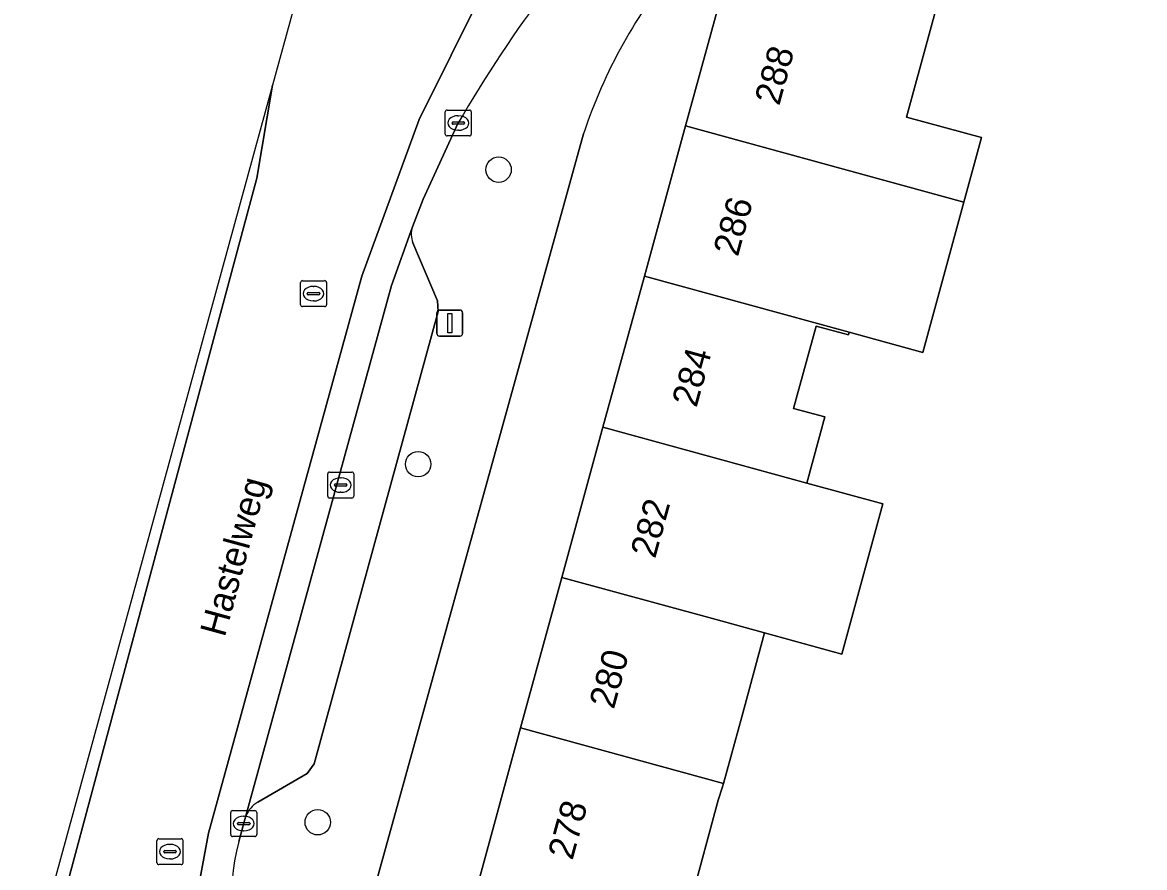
# Model space of a CAD drawing. Extents: x 158086 to 159499, y 382904 to 383981.
# Drawn here: x 158109.87 to 158153.07, y 383168.66 to 383201.21 of the extents above; entities that cross this region are included whole.
import ezdxf

# ---------------------------------------------------------------- set-up
doc = ezdxf.new("R2010")
doc.units = 0
for name, color, linetype in [('IMGEO_Boom', 7, 'Continuous'), ('IMGEO_Erf', 7, 'Continuous'), ('IMGEO_Kolk', 7, 'Continuous'), ('IMGEO_Lichtmast', 7, 'Continuous'), ('IMGEO_Openbare_ruimte_label', 7, 'Continuous'), ('IMGEO_Pand', 7, 'Continuous'), ('IMGEO_Pand_nummerreeks', 7, 'Continuous'), ('IMGEO_Parkeervlak_open', 7, 'Continuous'), ('IMGEO_Rijbaan_lokaal_gesloten', 7, 'Continuous'), ('IMGEO_Rioolput', 7, 'Continuous'), ('IMGEO_Voetpad_open', 7, 'Continuous')]:
    doc.layers.add(name, color=color, linetype=linetype)

msp = doc.modelspace()

# ---------------------------------------------------------------- linework, layer by layer
at = {"layer": 'IMGEO_Boom'}
for centre in [(158128.198, 383195.54), (158125.102, 383184.199), (158121.236, 383170.41)]:
    msp.add_circle(centre, 0.489, dxfattribs=at)
at = {"layer": 'IMGEO_Erf'}
for points in [[(158145.614, 383203.826), (158143.901, 383197.567), (158146.795, 383196.776), (158146.115, 383194.289), (158144.532, 383188.501), (158141.69, 383189.278), (158141.663, 383189.18), (158140.426, 383189.519), (158139.557, 383186.348), (158140.763, 383186.017), (158140.066, 383183.473), (158142.994, 383182.671), (158141.406, 383176.886), (158138.441, 383177.7), (158137.559, 383174.463), (158136.856, 383171.899), (158136.823, 383171.777), (158136.657, 383171.255), (158135.955, 383168.694), (158135.236, 383166.071), (158133.867, 383161.076), (158144.952, 383157.529), (158146.228, 383161.583), (158153.322, 383159.318)], [(158124.547, 383163.99), (158125.14, 383163.802), (158130.42, 383162.036), (158131.785, 383167.017), (158127.445, 383168.206), (158129.043, 383174.04), (158130.633, 383179.84), (158132.217, 383185.624), (158133.81, 383191.437), (158135.396, 383197.227), (158136.998, 383203.073)], [(158131.469, 383196.918), (158123.046, 383166.519)]]:
    msp.add_lwpolyline(points, dxfattribs=at)
msp.add_arc((158150.374, 383190.692), 19.904, 139.9318, 161.7716, dxfattribs=at)
at = {"layer": 'IMGEO_Kolk'}
for p, q in [((158126.147, 383196.912), (158126.147, 383197.764)), ((158126.222, 383197.838), (158127.074, 383197.838)), ((158126.635, 383197.618), (158126.66, 383197.618)), ((158127.148, 383197.764), (158127.148, 383196.912)), ((158126.406, 383197.332), (158126.406, 383197.344)), ((158126.844, 383197.295), (158126.446, 383197.295)), ((158126.449, 383197.381), (158126.847, 383197.381)), ((158126.89, 383197.344), (158126.89, 383197.332)), ((158127.074, 383196.838), (158126.222, 383196.838)), ((158126.658, 383197.058), (158126.633, 383197.058)), ((158121.62, 383182.97), (158121.62, 383183.822)), ((158121.695, 383183.896), (158122.547, 383183.896)), ((158122.621, 383183.822), (158122.621, 383182.97)), ((158121.879, 383183.39), (158121.879, 383183.402)), ((158122.317, 383183.353), (158121.919, 383183.353)), ((158121.922, 383183.439), (158122.32, 383183.439)), ((158122.108, 383183.676), (158122.133, 383183.676)), ((158122.363, 383183.402), (158122.363, 383183.39)), ((158122.547, 383182.896), (158121.695, 383182.896)), ((158122.131, 383183.116), (158122.106, 383183.116)), ((158117.887, 383169.932), (158117.887, 383170.784)), ((158117.962, 383170.858), (158118.814, 383170.858)), ((158118.888, 383170.784), (158118.888, 383169.932)), ((158118.146, 383170.352), (158118.146, 383170.364)), ((158118.189, 383170.401), (158118.587, 383170.401)), ((158118.375, 383170.638), (158118.4, 383170.638)), ((158118.63, 383170.364), (158118.63, 383170.352)), ((158118.584, 383170.315), (158118.186, 383170.315)), ((158118.398, 383170.078), (158118.373, 383170.078)), ((158118.814, 383169.858), (158117.962, 383169.858))]:
    msp.add_line(p, q, dxfattribs=at)
for points in [[(158126.147, 383196.912), (158126.147, 383197.764)], [(158126.222, 383197.838), (158127.074, 383197.838)], [(158127.148, 383197.764), (158127.148, 383196.912)], [(158127.074, 383196.838), (158126.222, 383196.838)], [(158121.62, 383182.97), (158121.62, 383183.822)], [(158121.695, 383183.896), (158122.547, 383183.896)], [(158122.621, 383183.822), (158122.621, 383182.97)], [(158122.547, 383182.896), (158121.695, 383182.896)], [(158117.887, 383169.932), (158117.887, 383170.784)], [(158117.962, 383170.858), (158118.814, 383170.858)], [(158118.888, 383170.784), (158118.888, 383169.932)], [(158118.814, 383169.858), (158117.962, 383169.858)]]:
    msp.add_lwpolyline(points, dxfattribs=at)
for centre, radius, start, end in [((158126.224, 383197.762), 0.0765, 91.552, 178.448), ((158126.224, 383197.762), 0.0765, 91.552, 178.448), ((158127.072, 383197.762), 0.0765, 1.552, 88.448), ((158127.072, 383197.762), 0.0765, 1.552, 88.448), ((158126.446, 383197.341), 0.0403, 85.8775, 175.7526), ((158126.443, 383197.331), 0.0366, 178.938, 274.7102), ((158126.847, 383197.338), 0.043, 264.8664, 352.4533), ((158126.851, 383197.343), 0.0386, 1.7309, 96.639), ((158126.224, 383196.914), 0.0765, 181.552, 268.448), ((158126.224, 383196.914), 0.0765, 181.552, 268.448), ((158127.072, 383196.914), 0.0765, 271.552, 358.448), ((158127.072, 383196.914), 0.0765, 271.552, 358.448), ((158121.697, 383183.82), 0.0765, 91.552, 178.448), ((158121.697, 383183.82), 0.0765, 91.552, 178.448), ((158122.545, 383183.82), 0.0765, 1.552, 88.448), ((158122.545, 383183.82), 0.0765, 1.552, 88.448), ((158121.919, 383183.399), 0.0403, 85.8775, 175.7526), ((158121.916, 383183.389), 0.0366, 178.938, 274.7102), ((158122.32, 383183.396), 0.043, 264.8664, 352.4533), ((158122.324, 383183.401), 0.0386, 1.7309, 96.639), ((158121.697, 383182.972), 0.0765, 181.552, 268.448), ((158121.697, 383182.972), 0.0765, 181.552, 268.448), ((158122.545, 383182.972), 0.0765, 271.552, 358.448), ((158122.545, 383182.972), 0.0765, 271.552, 358.448), ((158117.964, 383170.782), 0.0765, 91.552, 178.448), ((158117.964, 383170.782), 0.0765, 91.552, 178.448), ((158118.812, 383170.782), 0.0765, 1.552, 88.448), ((158118.812, 383170.782), 0.0765, 1.552, 88.448), ((158118.186, 383170.361), 0.0403, 85.8775, 175.7526), ((158118.183, 383170.351), 0.0366, 178.938, 274.7102), ((158118.587, 383170.358), 0.043, 264.8664, 352.4533), ((158118.591, 383170.363), 0.0386, 1.7309, 96.639), ((158117.964, 383169.934), 0.0765, 181.552, 268.448), ((158117.964, 383169.934), 0.0765, 181.552, 268.448), ((158118.812, 383169.934), 0.0765, 271.552, 358.448), ((158118.812, 383169.934), 0.0765, 271.552, 358.448)]:
    msp.add_arc(centre, radius, start, end, dxfattribs=at)
for centre, major_axis, ratio, start_param, end_param in [((158126.634, 383197.338), (-0.387, 0.002), 0.722429, 4.712389, 7.853982), ((158126.659, 383197.338), (-0.39, 0.002), 0.717154, 1.570796, 4.712389), ((158122.107, 383183.396), (-0.387, 0.002), 0.722429, 4.712389, 7.853982), ((158122.132, 383183.396), (-0.39, 0.002), 0.717154, 1.570796, 4.712389), ((158118.374, 383170.358), (-0.387, 0.002), 0.722429, 4.712389, 7.853982), ((158118.399, 383170.358), (-0.39, 0.002), 0.717154, 1.570796, 4.712389)]:
    msp.add_ellipse(centre, major_axis=major_axis, ratio=ratio, start_param=start_param, end_param=end_param, dxfattribs=at)
at = {"layer": 'IMGEO_Lichtmast'}
for p, q in [((158125.824, 383189.233), (158125.824, 383190.033)), ((158125.824, 383190.033), (158125.824, 383189.233)), ((158125.924, 383190.133), (158126.714, 383190.133)), ((158126.714, 383190.133), (158125.924, 383190.133)), ((158126.814, 383190.033), (158126.814, 383189.233)), ((158126.814, 383189.233), (158126.814, 383190.033)), ((158126.714, 383189.133), (158125.924, 383189.133)), ((158125.924, 383189.133), (158126.714, 383189.133))]:
    msp.add_line(p, q, dxfattribs=at)
msp.add_lwpolyline([(158126.244, 383190.008), (158126.394, 383190.008), (158126.394, 383189.258), (158126.244, 383189.258), (158126.244, 383190.008)], dxfattribs=at)
for centre, start, end in [((158125.924, 383190.033), 90, 180), ((158125.924, 383190.033), 90, 180), ((158126.714, 383190.033), 0, 90), ((158126.714, 383190.033), 360, 90), ((158125.924, 383189.233), 180, 270), ((158125.924, 383189.233), 180, 270), ((158126.714, 383189.233), 270, 0), ((158126.714, 383189.233), 270, 0)]:
    msp.add_arc(centre, 0.1, start, end, dxfattribs=at)
at = {"layer": 'IMGEO_Pand'}
for points in [[(158135.396, 383197.227), (158146.115, 383194.289), (158146.795, 383196.776), (158143.901, 383197.567), (158145.614, 383203.826), (158141.177, 383205.04), (158140.384, 383202.146), (158136.998, 383203.073)], [(158146.115, 383194.289), (158135.396, 383197.227), (158133.81, 383191.437), (158141.69, 383189.278), (158144.532, 383188.501)], [(158140.066, 383183.473), (158140.763, 383186.017), (158139.557, 383186.348), (158140.426, 383189.519), (158141.663, 383189.18), (158141.69, 383189.278), (158133.81, 383191.437), (158132.217, 383185.624)], [(158142.994, 383182.671), (158140.066, 383183.473), (158132.217, 383185.624), (158130.633, 383179.84), (158136.43, 383178.251), (158138.441, 383177.7), (158141.406, 383176.886)], [(158138.441, 383177.7), (158136.43, 383178.251), (158130.633, 383179.84), (158129.043, 383174.04), (158136.856, 383171.899), (158137.559, 383174.463)], [(158136.856, 383171.899), (158129.043, 383174.04), (158127.445, 383168.206), (158131.785, 383167.017), (158130.42, 383162.036), (158133.867, 383161.076), (158135.236, 383166.071), (158135.955, 383168.694), (158136.657, 383171.255), (158136.823, 383171.777)]]:
    msp.add_lwpolyline(points, close=True, dxfattribs=at)
at = {"layer": 'IMGEO_Parkeervlak_open'}
for points in [[(158124.881, 383193.345), (158124.08, 383191.076), (158118.475, 383170.654)], [(158118.926, 383171.179), (158120.832, 383172.293), (158121.096, 383172.659), (158125.876, 383190.077), (158125.846, 383190.485), (158124.904, 383192.718)]]:
    msp.add_lwpolyline(points, dxfattribs=at)
for centre, radius, start, end in [((158125.75, 383193.063), 0.914, 162.0162, 202.1854), ((158119.47, 383170.256), 1.071, 120.4898, 158.1819)]:
    msp.add_arc(centre, radius, start, end, dxfattribs=at)
at = {"layer": 'IMGEO_Rijbaan_lokaal_gesloten'}
for points in [[(158124.452, 383206.638), (158124.819, 383209.324), (158122.442, 383209.544), (158119.498, 383198.799), (158118.896, 383195.213), (158111.593, 383168.013), (158111.383, 383166.817), (158111.299, 383165.033), (158111.404, 383163.963), (158111.855, 383161.854), (158112.421, 383160.267), (158113.174, 383158.889), (158113.975, 383157.813), (158114.447, 383157.32), (158121.663, 383155.026)], [(158121.663, 383155.026), (158123.545, 383158.624), (158121.299, 383159.472), (158120.511, 383159.893), (158119.732, 383160.433), (158118.989, 383161.105), (158118.281, 383161.896), (158117.694, 383162.772), (158117.166, 383163.887), (158116.819, 383164.93), (158116.651, 383166.022), (158116.603, 383167.245), (158116.699, 383168.192), (158117.038, 383169.988), (158122.934, 383191.435), (158125.143, 383197.468), (158128.824, 383204.89), (158128.837, 383205.106), (158130.117, 383208.788), (158126.371, 383208.986), (158125.437, 383206.357)], [(158128.824, 383204.89), (158125.143, 383197.468), (158122.934, 383191.435), (158117.038, 383169.988), (158116.699, 383168.192), (158116.603, 383167.245), (158116.651, 383166.022), (158116.819, 383164.93), (158117.166, 383163.887), (158117.694, 383162.772), (158118.281, 383161.896), (158118.989, 383161.105), (158119.732, 383160.433), (158120.511, 383159.893), (158121.299, 383159.472), (158123.545, 383158.624), (158123.906, 383159.769), (158123.083, 383160.025)], [(158114.447, 383157.32), (158113.975, 383157.813), (158113.174, 383158.889), (158112.421, 383160.267), (158111.855, 383161.854), (158111.404, 383163.963), (158111.299, 383165.033), (158111.383, 383166.817), (158111.593, 383168.013), (158118.896, 383195.213), (158119.498, 383198.799), (158109.869, 383163.66)], [(158124.08, 383191.076), (158124.881, 383193.345), (158125.29, 383194.403), (158126.648, 383197.338)], [(158118.195, 383169.67), (158118.475, 383170.654), (158124.08, 383191.076)]]:
    msp.add_lwpolyline(points, dxfattribs=at)
for centre, radius, start, end in [((158170.784, 383171.834), 50.975, 142.9358, 149.9784), ((158126.058, 383167.594), 8.132, 165.2065, 248.5444)]:
    msp.add_arc(centre, radius, start, end, dxfattribs=at)
at = {"layer": 'IMGEO_Rioolput'}
for p, q in [((158120.574, 383190.34), (158120.574, 383191.192)), ((158120.649, 383191.266), (158121.501, 383191.266)), ((158121.575, 383191.192), (158121.575, 383190.34)), ((158120.833, 383190.76), (158120.833, 383190.772)), ((158121.271, 383190.723), (158120.873, 383190.723)), ((158120.876, 383190.809), (158121.274, 383190.809)), ((158121.062, 383191.046), (158121.087, 383191.046)), ((158121.317, 383190.772), (158121.317, 383190.76)), ((158121.501, 383190.266), (158120.649, 383190.266)), ((158121.085, 383190.486), (158121.06, 383190.486)), ((158115.049, 383168.851), (158115.049, 383169.703)), ((158115.124, 383169.777), (158115.976, 383169.777)), ((158115.537, 383169.557), (158115.562, 383169.557)), ((158116.05, 383169.703), (158116.05, 383168.851)), ((158115.308, 383169.271), (158115.308, 383169.283)), ((158115.746, 383169.234), (158115.348, 383169.234)), ((158115.351, 383169.32), (158115.749, 383169.32)), ((158115.792, 383169.283), (158115.792, 383169.271)), ((158115.976, 383168.777), (158115.124, 383168.777)), ((158115.56, 383168.997), (158115.535, 383168.997))]:
    msp.add_line(p, q, dxfattribs=at)
for points in [[(158120.574, 383190.34), (158120.574, 383191.192)], [(158120.649, 383191.266), (158121.501, 383191.266)], [(158121.575, 383191.192), (158121.575, 383190.34)], [(158121.501, 383190.266), (158120.649, 383190.266)], [(158115.049, 383168.851), (158115.049, 383169.703)], [(158115.124, 383169.777), (158115.976, 383169.777)], [(158116.05, 383169.703), (158116.05, 383168.851)], [(158115.976, 383168.777), (158115.124, 383168.777)]]:
    msp.add_lwpolyline(points, dxfattribs=at)
for centre, radius, start, end in [((158120.651, 383191.19), 0.0765, 91.552, 178.448), ((158120.651, 383191.19), 0.0765, 91.552, 178.448), ((158121.499, 383191.19), 0.0765, 1.552, 88.448), ((158121.499, 383191.19), 0.0765, 1.552, 88.448), ((158120.873, 383190.769), 0.0403, 85.8775, 175.7526), ((158120.87, 383190.759), 0.0366, 178.938, 274.7102), ((158121.274, 383190.766), 0.043, 264.8664, 352.4533), ((158121.278, 383190.771), 0.0386, 1.7309, 96.639), ((158120.651, 383190.342), 0.0765, 181.552, 268.448), ((158120.651, 383190.342), 0.0765, 181.552, 268.448), ((158121.499, 383190.342), 0.0765, 271.552, 358.448), ((158121.499, 383190.342), 0.0765, 271.552, 358.448), ((158115.126, 383169.701), 0.0765, 91.552, 178.448), ((158115.126, 383169.701), 0.0765, 91.552, 178.448), ((158115.974, 383169.701), 0.0765, 1.552, 88.448), ((158115.974, 383169.701), 0.0765, 1.552, 88.448), ((158115.348, 383169.28), 0.0403, 85.8775, 175.7526), ((158115.345, 383169.27), 0.0366, 178.938, 274.7102), ((158115.749, 383169.277), 0.043, 264.8664, 352.4533), ((158115.753, 383169.282), 0.0386, 1.7309, 96.639), ((158115.126, 383168.853), 0.0765, 181.552, 268.448), ((158115.126, 383168.853), 0.0765, 181.552, 268.448), ((158115.974, 383168.853), 0.0765, 271.552, 358.448), ((158115.974, 383168.853), 0.0765, 271.552, 358.448)]:
    msp.add_arc(centre, radius, start, end, dxfattribs=at)
for centre, major_axis, ratio, start_param, end_param in [((158121.061, 383190.766), (-0.387, 0.002), 0.722429, 4.712389, 7.853982), ((158121.086, 383190.766), (-0.39, 0.002), 0.717154, 1.570796, 4.712389), ((158115.536, 383169.277), (-0.387, 0.002), 0.722429, 4.712389, 7.853982), ((158115.561, 383169.277), (-0.39, 0.002), 0.717154, 1.570796, 4.712389)]:
    msp.add_ellipse(centre, major_axis=major_axis, ratio=ratio, start_param=start_param, end_param=end_param, dxfattribs=at)
at = {"layer": 'IMGEO_Voetpad_open'}
for points in [[(158126.648, 383197.338), (158125.29, 383194.403), (158124.881, 383193.345)], [(158123.046, 383166.519), (158131.469, 383196.918)], [(158124.904, 383192.718), (158125.846, 383190.485), (158125.876, 383190.077), (158121.096, 383172.659), (158120.832, 383172.293), (158118.926, 383171.179)], [(158118.475, 383170.654), (158118.195, 383169.67)]]:
    msp.add_lwpolyline(points, dxfattribs=at)
for centre, radius, start, end in [((158150.374, 383190.692), 19.904, 139.9318, 161.7716), ((158170.784, 383171.834), 50.975, 142.9358, 149.9784), ((158125.75, 383193.063), 0.914, 162.0162, 202.1854), ((158119.47, 383170.256), 1.071, 120.4898, 158.1819), ((158126.058, 383167.594), 8.132, 165.2065, 248.5444)]:
    msp.add_arc(centre, radius, start, end, dxfattribs=at)

# ---------------------------------------------------------------- texts
at = {"layer": 'IMGEO_Openbare_ruimte_label'}
msp.add_text('Hastelweg', height=1, rotation=74.7549, dxfattribs=at).set_placement((158117.655, 383177.507))
at = {"layer": 'IMGEO_Pand_nummerreeks'}
for s, rotation, p in [('288', 74.6779, (158139.002, 383197.975)), ('286', 74.6793, (158137.41, 383192.161)), ('284', 74.6779, (158135.817, 383186.35)), ('282', 74.6793, (158134.224, 383180.536)), ('280', 74.6793, (158132.634, 383174.73)), ('278', 74.6793, (158131.042, 383168.919))]:
    msp.add_text(s, height=1, rotation=rotation, dxfattribs=at).set_placement(p)

doc.saveas('drawing.dxf')
